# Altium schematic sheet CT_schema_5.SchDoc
size 397 x 245 mm
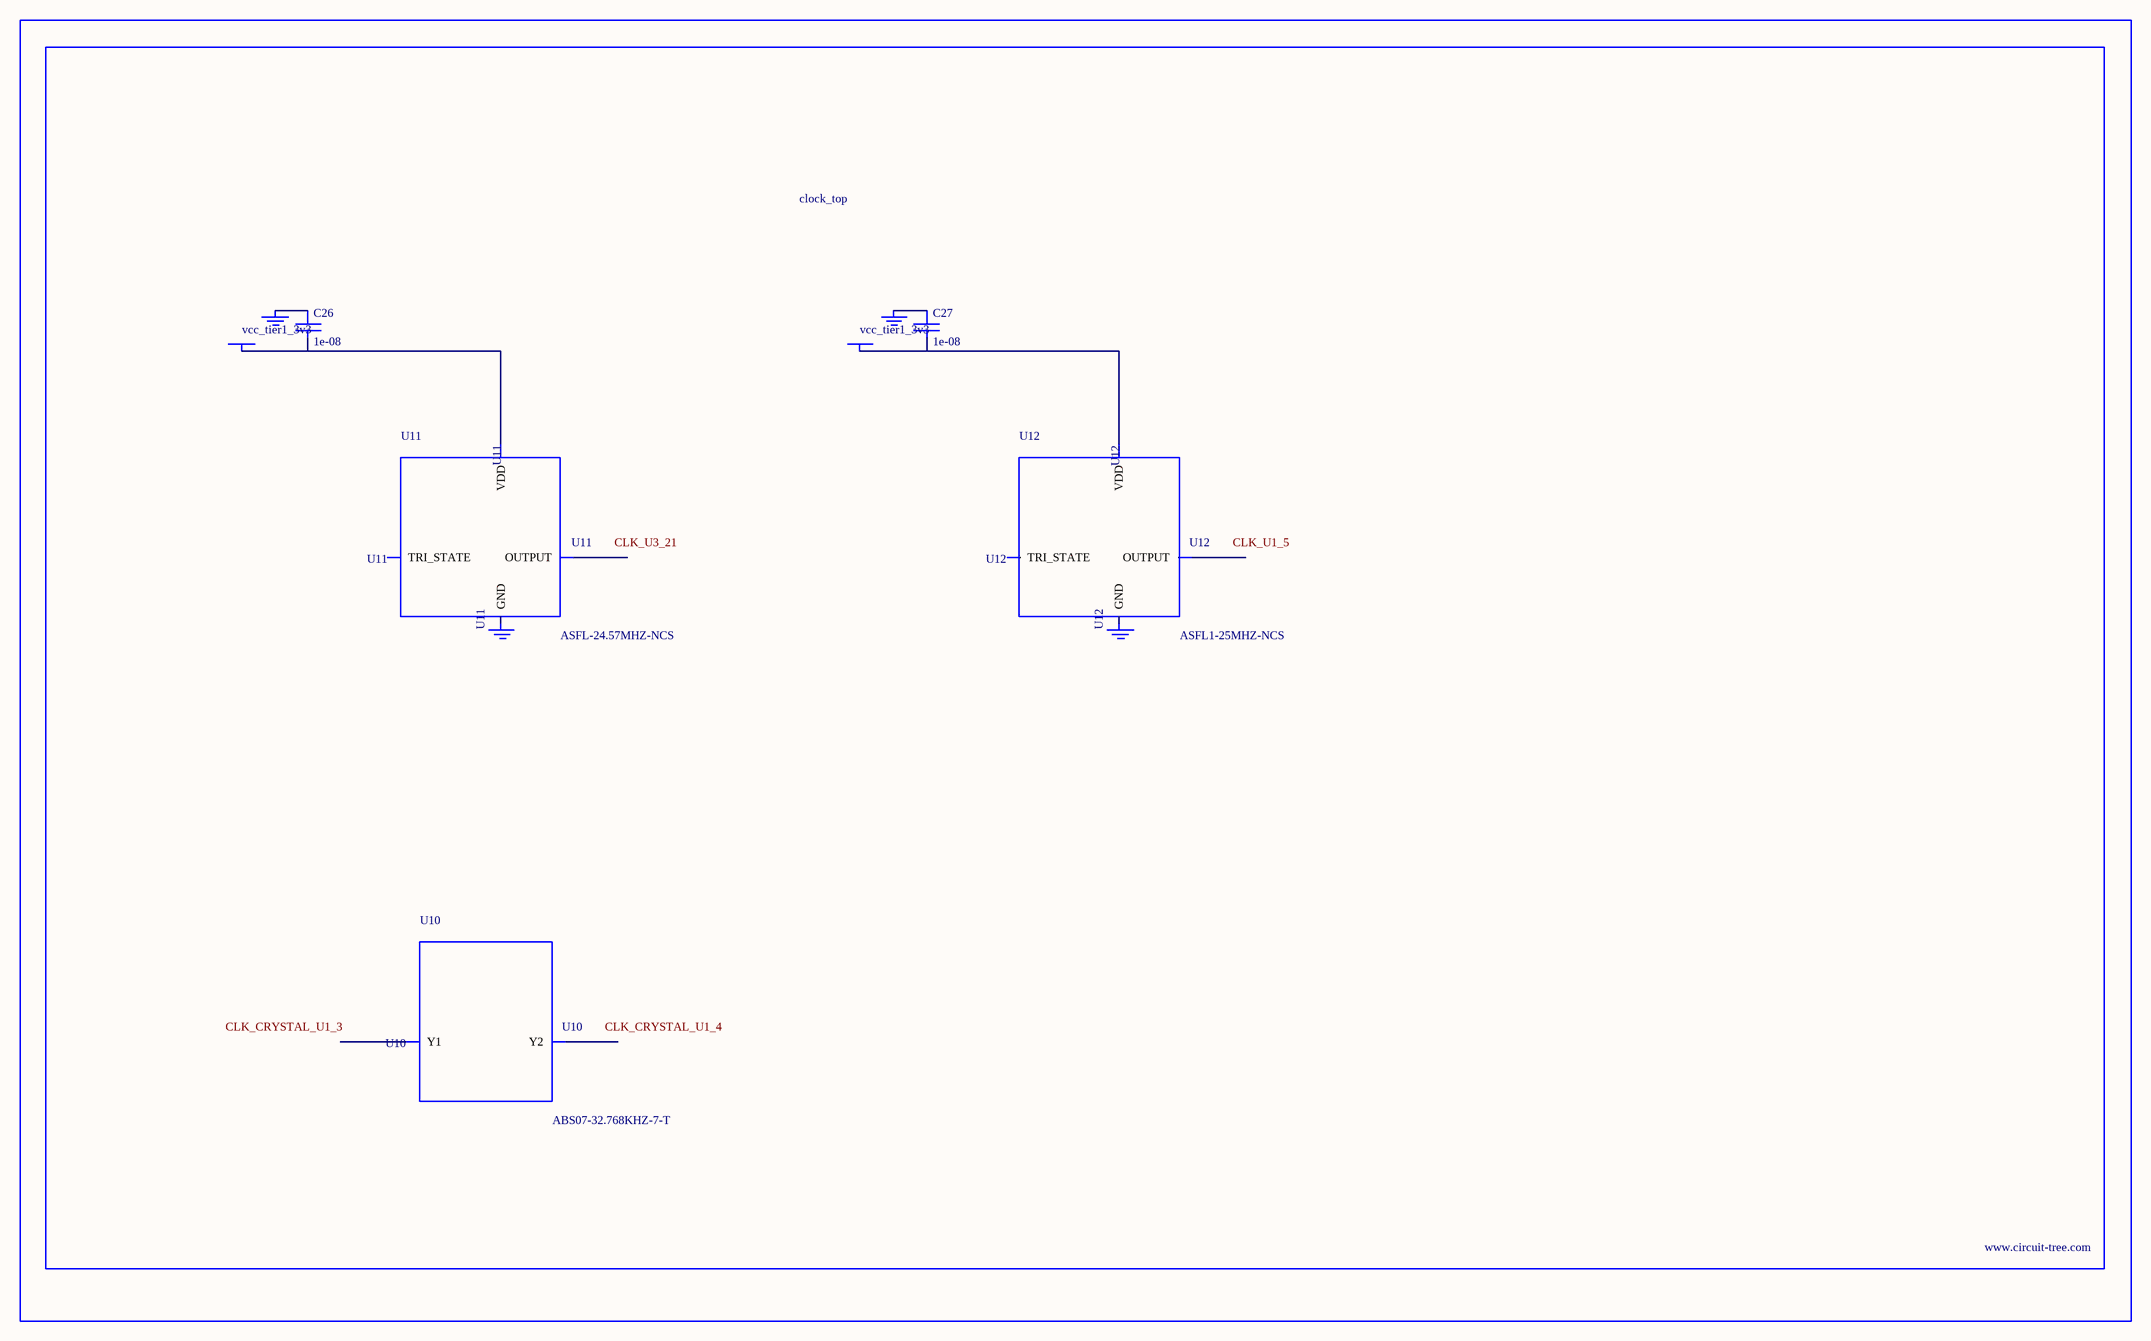
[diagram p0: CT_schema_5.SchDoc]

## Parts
BORDER4  (no value)
C26  1e-08  [C0402]
C27  1e-08  [C0402]
GND_INSTANCE_4_0  (no value)
GND_INSTANCE_4_1  (no value)
GND_INSTANCE_4_2  (no value)
GND_INSTANCE_4_3  (no value)
POWER_INSTANCE_4_0  vcc_tier1_3v3
POWER_INSTANCE_4_1  vcc_tier1_3v3
U10  ABS07-32.768KHZ-7-T  [ABS07-32.768KHZ-7-T]
U11  ASFL-24.57MHZ-NCS  [ASFL1]
U12  ASFL1-25MHZ-NCS  [ASFL1]

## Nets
NetC26_1: C26.1 GND_INSTANCE_4_0.0(GND)
NetC26_2: C26.2 POWER_INSTANCE_4_0.0(PWR) U11.4(VDD)
NetC27_1: C27.1 GND_INSTANCE_4_2.0(GND)
NetC27_2: C27.2 POWER_INSTANCE_4_1.0(PWR) U12.4(VDD)

Not connected (* = marked no-connect by the designer): GND_INSTANCE_4_1 0(GND); GND_INSTANCE_4_3 0(GND); U10 1(Y1) 2(Y2); U11 1(TRI_STATE) 2(GND) 3(OUTPUT); U12 1(TRI_STATE) 2(GND) 3(OUTPUT)

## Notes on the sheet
- Labels drawn without touching a wire or pin: CLK_CRYSTAL_U1_3, CLK_CRYSTAL_U1_4, CLK_U1_5, CLK_U3_21

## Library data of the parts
BORDER4 = BORDER_PAGE4
C26 C27 = C0402C103K3RAC
GND_INSTANCE_4_0-GND_INSTANCE_4_3 = GND
POWER_INSTANCE_4_0 POWER_INSTANCE_4_1 = PWR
